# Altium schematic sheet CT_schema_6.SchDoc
size 252 x 159 mm
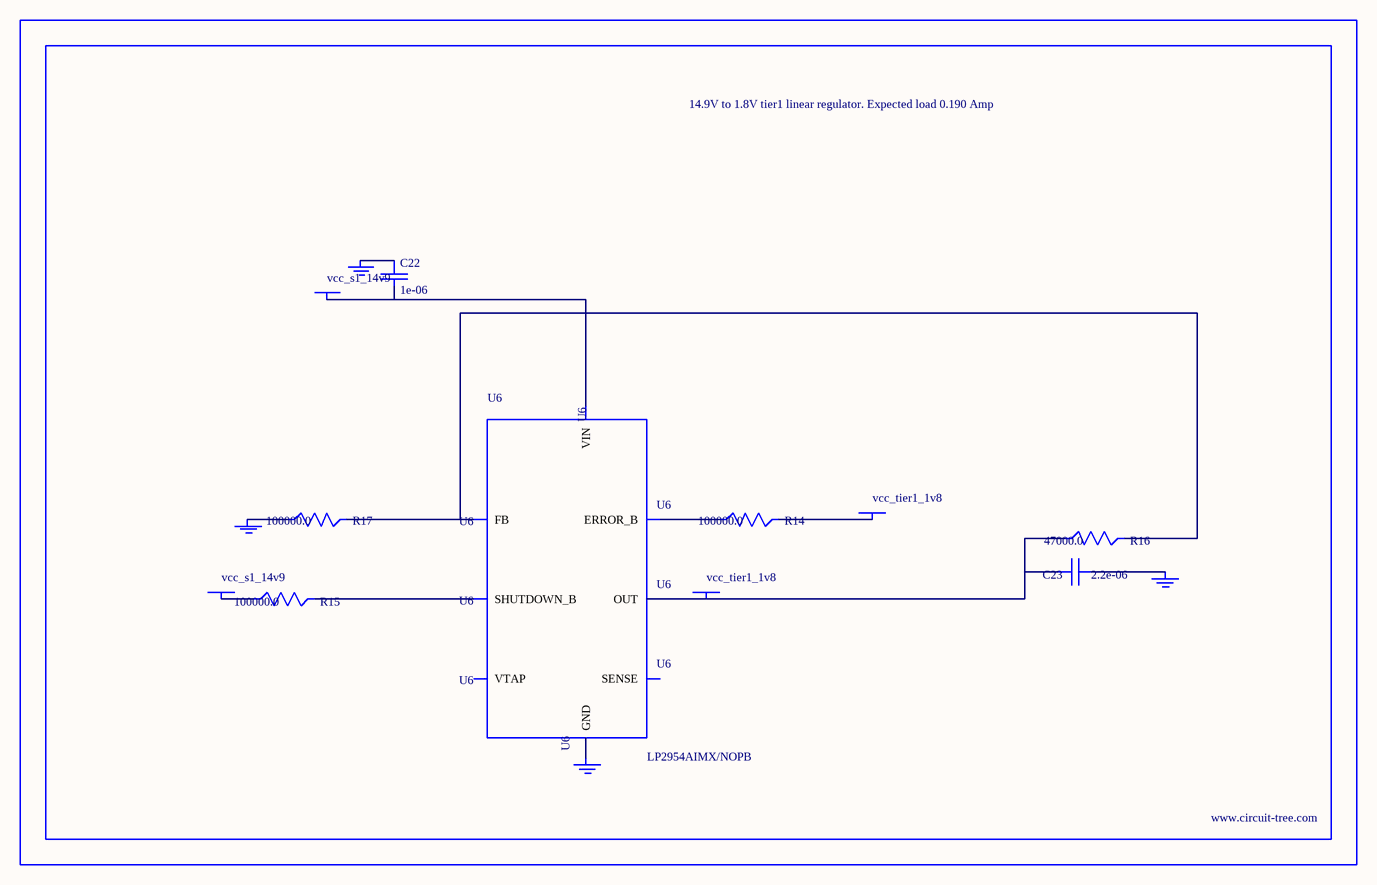
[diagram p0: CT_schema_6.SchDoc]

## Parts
BORDER5  (no value)
C22  1e-06  [EXV-9B]
C23  2.2e-06  [EXV-9B]
GND_INSTANCE_5_0  (no value)
GND_INSTANCE_5_1  (no value)
GND_INSTANCE_5_2  (no value)
GND_INSTANCE_5_3  (no value)
POWER_INSTANCE_5_0  vcc_s1_14v9
POWER_INSTANCE_5_1  vcc_tier1_1v8
POWER_INSTANCE_5_2  vcc_s1_14v9
POWER_INSTANCE_5_3  vcc_tier1_1v8
R14  100000.0  [R0603]
R15  100000.0  [R0603]
R16  47000.0  [R0603]
R17  100000.0  [R0603]
U6  LP2954AIMX/NOPB  [LP2954]

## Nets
NetC22_1: C22.1 GND_INSTANCE_5_2.0(GND)
NetC22_2: C22.2 POWER_INSTANCE_5_2.0(PWR) U6.8(VIN)
NetC23_1: C23.1 GND_INSTANCE_5_0.0(GND)
NetC23_2: C23.2 POWER_INSTANCE_5_3.0(PWR) R16.1 U6.1(OUT)
NetGND_INSTANCE_5_1_0: GND_INSTANCE_5_1.0(GND) R17.1
NetGND_INSTANCE_5_3_0: GND_INSTANCE_5_3.0(GND) U6.4(GND)
NetPOWER_INSTANCE_5_0_0: POWER_INSTANCE_5_0.0(PWR) R15.1
NetPOWER_INSTANCE_5_1_0: POWER_INSTANCE_5_1.0(PWR) R14.2
NetR14_1: R14.1 U6.5(ERROR_B)
NetR15_2: R15.2 U6.3(SHUTDOWN_B)
NetR16_2: R16.2 R17.2 U6.7(FB)

Not connected (* = marked no-connect by the designer): U6 2(SENSE) 6(VTAP)

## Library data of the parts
BORDER5 = BORDER_PAGE5
C22 = EDK105M050A9BAA
C23 = EDK225M050A9BAA
GND_INSTANCE_5_0-GND_INSTANCE_5_3 = GND
POWER_INSTANCE_5_0-POWER_INSTANCE_5_3 = PWR
R14 R15 R17 = RC0603JR-07100KL
R16 = RC0603JR-0747KL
